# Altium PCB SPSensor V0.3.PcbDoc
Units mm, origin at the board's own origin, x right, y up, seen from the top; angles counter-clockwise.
Board outline 22.01 x 110.07 mm, 4 copper layers (TopLayer, GND, PWR, BottomLayer); 88 components, 66 nets, 299 pads, 113 vias.
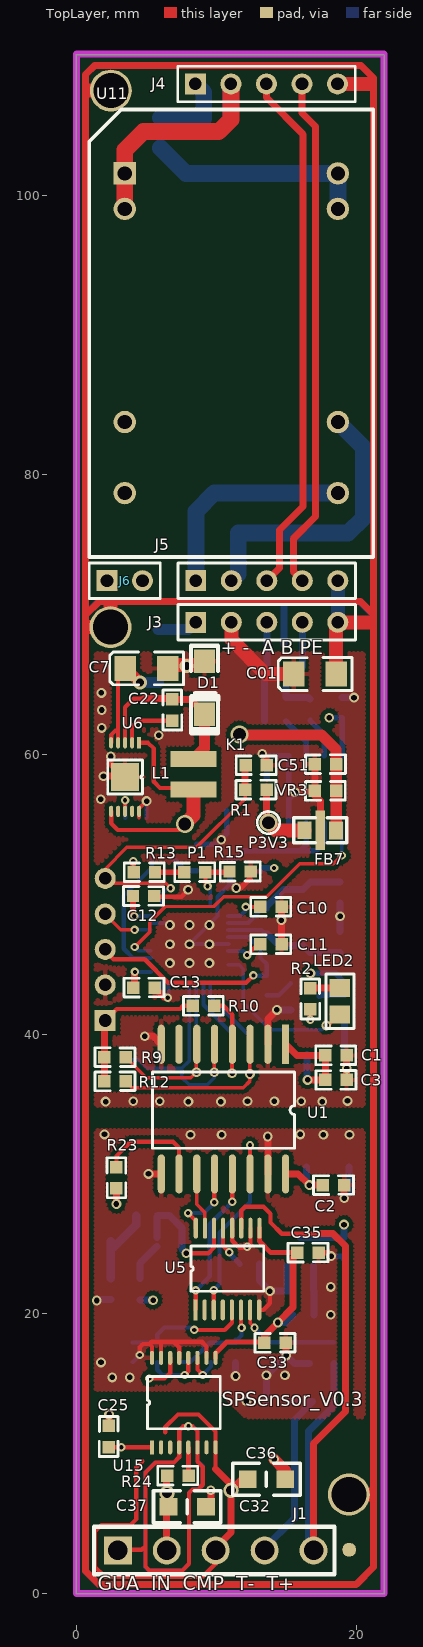
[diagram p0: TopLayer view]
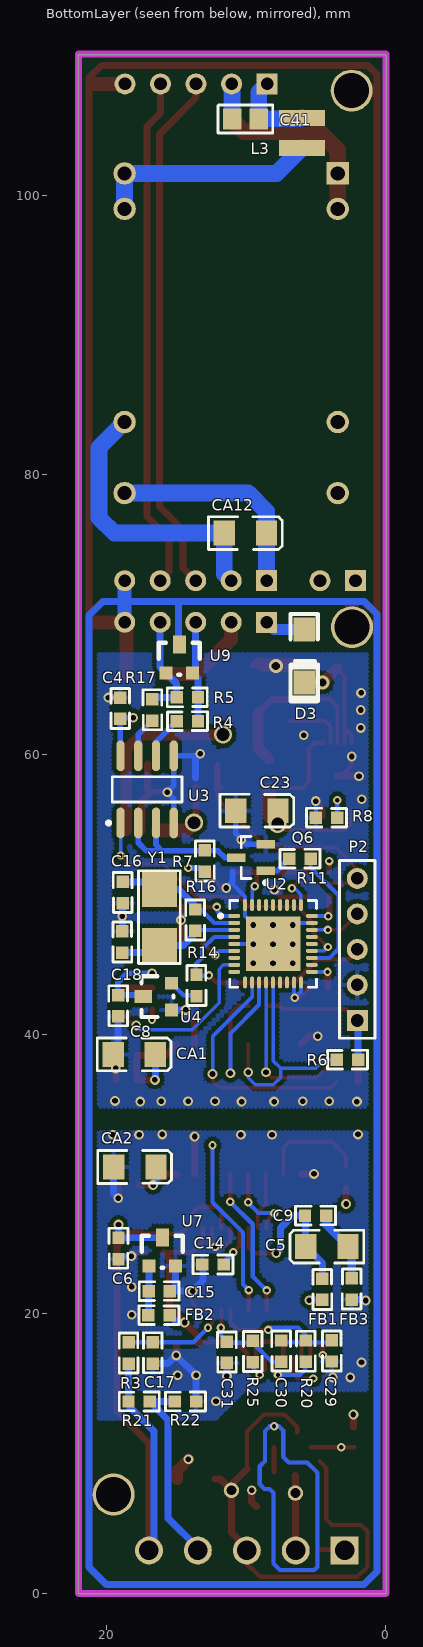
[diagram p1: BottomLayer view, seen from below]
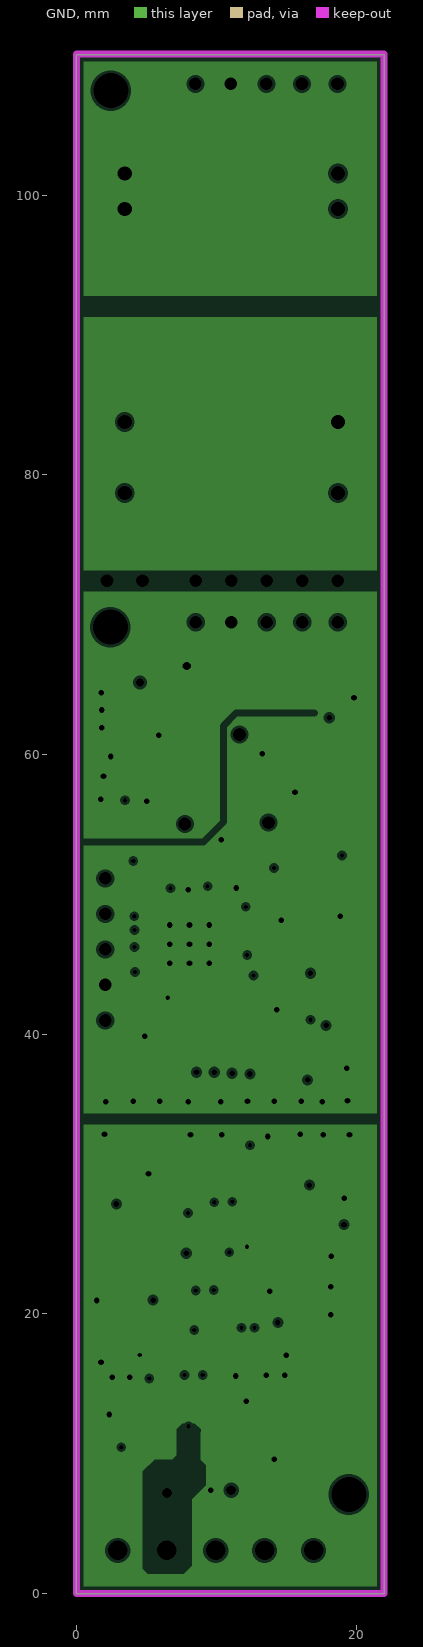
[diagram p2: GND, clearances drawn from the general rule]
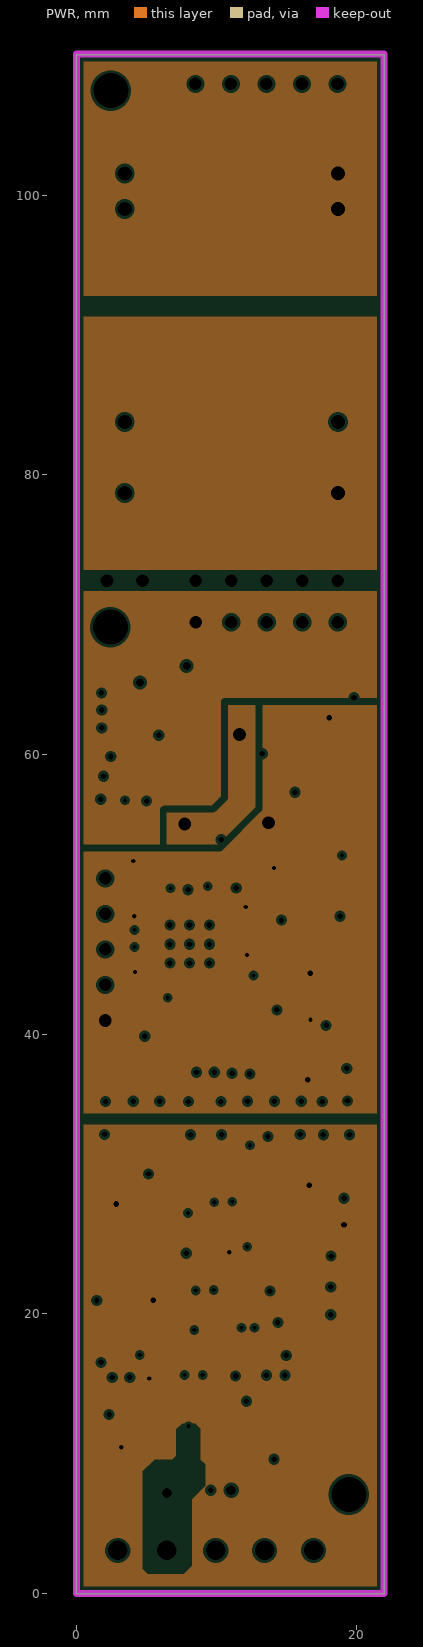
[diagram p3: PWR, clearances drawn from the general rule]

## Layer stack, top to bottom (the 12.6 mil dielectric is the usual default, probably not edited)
TopLayer: signal copper 0.0356
Dielectric: core 0.32, FR-4, Dk 4.8
GND: plane copper 0.0356, net (Multiple Nets)
Dielectric: prepreg 0.32, FR-4, Dk 4.8
PWR: plane copper 0.0356, net (Multiple Nets)
Dielectric: core 0.32, FR-4, Dk 4.8
BottomLayer: signal copper 0.0356

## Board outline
-0.006,-0.025 22,-0.025 22,110.05 -0.006,110.05

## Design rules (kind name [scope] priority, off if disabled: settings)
Clearance Clearance_poly [InPolygon] p1: gap=0.3
Clearance [All] p2: gap=0.15
ComponentClearance [All] p1: gap=0.15 collisioncheckmode=3 verticalgap=0.254 showdistances=FALSE
FabricationTestPointUsage TestPointUsage [All] p1: valid=0 allowmultiple=FALSE
FabricationTestpoint Testpoint [All] p1: side=3 testpointundercomponent=TRUE minsize=1.016 maxsize=2.54 preferedsize=1.524 minholesize=0.508 maxholesize=1.016 preferedholesize=0.813 testpointgrid=0.025 allowsidetop=TRUE allowsidebottom=TRUE usegrid=TRUE gridtolerance=0
HoleSize [All] p1: absolutevalues=TRUE maxlimit=5.08 minlimit=0.025 maxpercent=80.000 minpercent=20.000
MinimumSolderMaskSliver [All] p1: minsoldermaskwidth=0.15
PlaneClearance [All] p1: clearance=0.2
PlaneConnect [All] p1: planeconnectstyle=Relief reliefexpansion=0.3 reliefentries=4 reliefconductorwidth=0.3 reliefairgap=0.3
PolygonConnect PolygonConnect_via [IsVia] p1: connectstyle=Direct reliefconductorwidth=0.254 reliefentries=4 polygonreliefangle="90 Angle"
PolygonConnect [All] p2: connectstyle=Relief reliefconductorwidth=0.3 reliefentries=4 polygonreliefangle="90 Angle"
RoutingVias [All] p1: holewidth=0.305 width=0.61 viastyle="Through Hole" minholewidth=0.254 minwidth=0.508 maxholewidth=2 maxwidth=5
SilkToSilkClearance [All] p1: silktosilkclearance=0
SilkscreenOverComponentPads [All] p1: minsilkscreentomaskgap=0
SolderMaskExpansion [All] p1: expansion=0.102
Width [All] p1: maxlimit=5.08 minlimit=0.1 preferedwidth=0.254
19 further rules are at their usual default settings.

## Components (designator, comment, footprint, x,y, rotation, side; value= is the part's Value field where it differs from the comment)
C1 "10nF" SM0603 18.55,38.525 r0 top
C01 "1nF/2kV" SM1206 17.05,65.75 r180 top
C2 "0.1uF" SM0603 18.375,29.25 r0 top
C3 "0.1uF" SM0603 18.55,36.675 r180 top
C4 "0.1uF" SM0603 19.05,63.3 r90 bottom
C5 "10uF" SM1206 4.225,24.8 r0 bottom
C6 "4.7uF" SM0603 19.075,24.675 r270 bottom
C7 "4.7uF/50V" SM1206 5,66.15 r180 top
C8 "0.1uF" SM0603 19.1,42.025 r270 bottom
C9 "0.1uF" SM0603 5.025,27.075 r180 bottom
C10 "0.1uF" SM0603 13.9,49.15 r0 top
C11 "0.1uF" SM0603 13.9,46.475 r0 top
C12 "0.1uF" SM0603 4.8,49.925 r0 top
C13 "0.1uF" SM0603 4.825,43.375 r0 top
C14 "0.1uF" SM0603 12.375,23.475 r0 bottom
C15 "1uF" SM0603 16.21,21.675 r180 bottom
C16 "22pF" SM0603 18.775,50.125 r270 bottom
C17 "1uF" SM0603 16.625,17.2 r270 bottom
C18 "22pF" SM0603 18.9,46.59 r90 bottom
C22 "0.47uF" SM0603 6.8,63.175 r90 top
C23 "22uF" SM1206 9.225,55.975 r180 bottom
C25 "0.1uF" SM0603 2.25,11.225 r90 top
C29 "1uF" SM0603 3.925,17.35 r90 bottom
C30 "100pF" SM0603 7.45,17.325 r270 bottom
C31 "1uF" SM0603 11.325,17.25 r270 bottom
C33 "0.1uF" SM0603 14.2,17.975 r0 top
C35 "0.1uF" SM0603 16.55,24.425 r0 top
C36 "1nF" 0805A 12.241,8.172 r0 top
C37 "1nF" 0805A 6.575,6.2 r0 top
C41 "1uF/50V" SM0805 10.025,105.475 r0 bottom
C51 "0.1uF" SM0603 17.8,59.25 r180 top
CA1 "10uF" SM1206 18,38.55 r180 bottom
CA2 "10uF" SM1206 17.96,30.5 r180 bottom
CA12 "10uF/50V" SM1206 10.05,75.825 r180 bottom
D1 "CD1607-B140" 1206D 9.15,66.475 r270 top
D3 "M7" 1206D 5.85,68.75 r270 bottom
FB1 "BLM18PG600SN1" SM0603 4.6,21.75 r90 bottom
FB2 "BLM18PG600SN1" SM0603 16.225,19.95 r180 bottom
FB3 "BLM18PG600SN1" SM0603 2.5,21.775 r90 bottom
FB7 "NFM21PC105B1C3" NFM21PC105 18.575,54.575 r180 top
J1 "Header 5" CON1x5-3.5mm 2.95,3.075 r0 top
J3 "Header 5" HDR1X5 8.525,69.45 r0 top
J4 "Header 5" HDR1X5 8.5,107.95 r0 top
J5 "Header 5" HDR1X5 8.525,72.425 r0 top
J6 "Header 5" HDR1X2 2.175,72.425 r0 top (schematic designator J5)
K1 "KEY1" SM0603 12.85,59.175 r180 top (schematic designator R1)
L1 "LPS3010-472ML" LPS3010 8.375,59.666 r270 top
L3 "4.7uH" LPS3010 6,105.525 r270 bottom
LED2 "RUN" SM0805 18.8,42.375 r270 top
P1 "NC" sm0603 8.45,51.525 r180 top
P2 "Header 5" HDR1X5 2.05,40.975 r90 bottom
P3V3 "TestPoint" "test point" 13.725,55.125 r90 top
Q6 "MMBT3904" SOT23_N 9.65,52.625 r0 bottom
R1 "10K" SM0603 12.825,57.425 r180 top
R2 "560R" SM0603 16.675,42.525 r90 top
R3 "10K" SM0603 18.45,17.2 r90 bottom
R4 "10R" SM0603 14.2,62.325 r0 bottom
R5 "120R" SM0603 14.2,64.125 r180 bottom
R6 "100K" SM0603 2.75,38.125 r0 bottom
R7 "4.7K" SM0603 12.9,52.375 r270 bottom
R8 "49.9K" SM0603 4.25,55.525 r180 bottom
R9 "100K" SM0603 2.75,38.4 r0 top
R10 "100K" SM0603 9.075,42.075 r0 top
R11 "1K" SM0603 6.15,52.5 r0 bottom
R12 "100K" SM0603 2.75,36.675 r0 top
R13 "1K" SM0603 4.85,51.625 r0 top
R14 "1K" SM0603 13.6,43.475 r90 bottom
R15 "100K" SM0603 11.7,51.575 r180 top
R16 "10M" SM0603 13.6,48.15 r270 bottom
R17 "10R" SM0603 16.65,63.185 r270 bottom
R20 "10K" SM0603 5.775,17.325 r90 bottom
R21 "NC" SM0603 17.65,13.675 r0 bottom
R22 "0R" SM0603 14.34,13.675 r0 bottom
R23 "4.7K" SM0603 2.9,29.725 r270 top
R24 "10M" SM0603 7.25,8.475 r0 top
R25 "10K" SM0603 9.575,17.3 r90 bottom
U1 "ADuM5401ARWZ" ADUM1401 14.95,39.275 r270 top
U2 "STM32F103T8U6" VFQN36_V 8.075,46.45 r180 bottom
U3 "MAX3485CSA" NSO8_N 17.075,57.5 r90 bottom
U4 "CAT809VTBI-GT3" SOT-23 17.475,44.061 r90 bottom
U5 "AD7793BRU" AD7793 10.795,23.2 r90 top
U6 "LT3971IMSE-3.3" LT3971 3.475,58.381 r180 top
U7 "AD1584BRTZ" SOT-23 14.614,25.575 r180 bottom
U9 "SM712.TCT" SOT-23 13.4,67.975 r180 bottom
U11 "URB2424ZP-6WR3" URB2424ZP-6WR3 3.45,101.55 r270 top locked
U15 "LMP91200" LMP91200 7.67,13.65 r0 top
VR3 "V3.5MLA0603N" SM0603 17.8,57.45 r0 top (schematic designator VA2)
Y1 "8MHz" CY5.4X4.6 16.2,50.325 r270 bottom

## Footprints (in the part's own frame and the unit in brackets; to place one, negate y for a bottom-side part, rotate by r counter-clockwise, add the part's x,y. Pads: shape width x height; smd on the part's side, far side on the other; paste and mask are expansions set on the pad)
0805A [mm]
  rect 1.27x1.27 smd: 1(0,0) 2(2.678,0)
  silkscreen extent -1.07,-1.14 3.75,1.14
1206D [mm]
  rect 1.7x1.524 smd: 1(-0.19,0.003) 2(3.61,0.003)
  silkscreen extent -1.3,-0.97 4.96,0.99
AD7793 [mm]
  rect 1.5x0.3 smd: 1(-2.921,2.286)
  oval 1.5x0.3 smd: 2(-2.921,1.636) 3(-2.921,0.986) 4(-2.921,0.336) 5(-2.921,-0.314) 6(-2.921,-0.964) 7(-2.921,-1.614) 8(-2.921,-2.264) 9(2.921,-2.286) 10(2.921,-1.636) 11(2.921,-0.986) 12(2.921,-0.336) 13(2.921,0.314) 14(2.921,0.964) 15(2.921,1.614) 16(2.921,2.264)
  silkscreen extent -1.59,-2.59 1.64,2.61
ADUM1401 [mm]
  rect 2.8x0.51 smd: 1(0,0)
  oval 2.8x0.51 smd: 2(0,-1.27) 3(0,-2.54) 4(0,-3.81) 5(0,-5.08) 6(0,-6.35) 7(0,-7.62) 8(0,-8.89) 9(9.271,-8.89) 10(9.271,-7.62) 11(9.271,-6.35) 12(9.271,-5.08) 13(9.271,-3.81) 14(9.271,-2.54) 15(9.271,-1.27) 16(9.271,0)
  silkscreen extent 1.99,-9.53 7.43,0.64
CON1x5-3.5mm [mm]
  rect 2x2 hole 1.4: 1(0,0)
  round 2 hole 1.4: 2(3.5,0) 3(7,0) 4(10.5,0) 5(14,0)
  silkscreen extent -1.7,-1.7 15.5,1.7
CY5.4X4.6 [mm]
  rect 2.5x2.5 smd: 1(-0.025,0) 2(4,0)
  silkscreen extent -1.35,-1.49 5.28,1.49
HDR1X2 [mm] "Connector; Header; 2 Position"
  rect 1.5x1.5 hole 0.9: 1(0,0)
  round 1.5 hole 0.9: 2(2.54,0)
  silkscreen extent -1.27,-1.27 3.81,1.27
HDR1X5 [mm] "Connector; Header; 5 Position"
  rect 1.5x1.5 hole 0.9: 1(0,0)
  round 1.5 hole 0.9: 2(2.54,0) 3(5.08,0) 4(7.62,0) 5(10.16,0)
  silkscreen extent -1.27,-1.27 11.43,1.27
LMP91200 [mm]
  rect 0.3x1 smd: 1(-2.275,-3.2)
  oval 0.3x1 smd: 2(-1.625,-3.2) 3(-0.975,-3.2) 4(-0.325,-3.2) 5(0.325,-3.2) 6(0.975,-3.2) 7(1.625,-3.2) 8(2.275,-3.2) 9(2.275,3.2) 10(1.625,3.2) 11(0.975,3.2) 12(0.325,3.2) 13(-0.325,3.2) 14(-0.975,3.2) 15(-1.625,3.2) 16(-2.275,3.2)
  silkscreen extent -2.6,-1.87 2.6,1.87
LPS3010 [mm]
  rect 1.14x3.3 smd: 1(0,0) 2(2.16,0)
LT3971 [mm]
  rect 0.28x0.8 smd: 1(-1,-2.45)
  oval 0.28x0.8 smd: 2(-0.5,-2.45) 3(0,-2.45) 4(0.5,-2.45) 5(1,-2.45) 6(1,2.45) 7(0.5,2.45) 8(0,2.45) 9(-0.5,2.45) 10(-1,2.45)
  rect 2x2 smd: 11(0,0)
  silkscreen extent -1.25,-1.21 1.25,1.22
NFM21PC105 [mm]
  rect 1x1.27 smd: 1(0.01,0.008) 2(2.286,0)
  rect 0.7x2.8 smd: 3(1.143,0)
  silkscreen extent -0.76,-0.89 3.05,0.89
NSO8_N [mm] "SOIC, 8-Leads, Body 4.9x3.9mm, Pitch 1.27mm, IPC Medium Density"
  oval 2.2x0.6 smd: 1(-2.4,1.905) 2(-2.4,0.635) 3(-2.4,-0.635) 4(-2.4,-1.905) 5(2.4,-1.905) 6(2.4,-0.635) 7(2.4,0.635) 8(2.4,1.905)
  silkscreen extent -2.52,-2.5 0.9,2.88, body extent -2,-2.5 2,2.5, height 1.75
SM0603 [mil]
  rect 35x35 smd: 1(-30,-2) 2(30,-2)
  silkscreen extent -57,-28 56,24
sm0603 [mil]
  rect 35x35 smd: 1(-30,-2) 2(30,-2)
  silkscreen extent -57,-28 56,24
SM0805 [mm]
  rect 1.3x1.5 smd: 1(-0.933,0.022) 2(0.967,0.022)
  silkscreen extent -1.93,-0.97 1.98,1.04
SM1206 [mil]
  rect 60x70 smd: 1(59.5,0) 2(-59.5,0)
  silkscreen extent -104,-46 104,46
SOT23_N [mm] "SOT23, 3-Leads, Body 2.9x1.3mm, Pitch 0.95mm, Lead Span 2.3mm, IPC Medium Density"
  rect 1.3x0.6 smd: 1(-1.05,0.95) 2(-1.05,-0.95) 3(1.05,0)
  silkscreen extent -1.17,-1.5 0.7,1.92, body extent -0.7,-1.5 0.7,1.5, height 1.1
SOT-23 [mil]
  rect 36x36 smd: 1(-91.86,-84.66) 2(-16.86,-84.66)
  rect 36x50 smd: 3(-53.86,-4.66)
  silkscreen extent -112,-90 3,0
"test point" [mm]
  round 1.3 hole 0.9: 1(0,0)
  silkscreen extent -0.8,-0.8 0.8,0.8
URB2424ZP-6WR3 [mm] "isolated DC-DC converter, 6W"
  rect 1.6x1.6 hole 1.016: 2(0,0)
  round 1.6 hole 1.016: 3(2.54,0) 9(17.78,0) 11(22.86,0) 14(22.86,15.24) 16(17.78,15.24) 22(2.54,15.24) 23(0,15.24)
  silkscreen extent -4.57,-2.54 27.43,17.78
VFQN36_V [mm] "QFN, 36-Leads, Body 6x6mm, Pitch 0.5mm, ST Recommended"
  oval 0.85x0.3 smd: 1(-2.775,2) 2(-2.775,1.5) 3(-2.775,1) 4(-2.775,0.5) 5(-2.775,0) 6(-2.775,-0.5) 7(-2.775,-1) 8(-2.775,-1.5) 9(-2.775,-2) 19(2.775,-2) 20(2.775,-1.5) 21(2.775,-1) 22(2.775,-0.5) 23(2.775,0) 24(2.775,0.5) 25(2.775,1) 26(2.775,1.5) 27(2.775,2)
  oval 0.3x0.85 smd: 10(-2,-2.755) 11(-1.5,-2.755) 12(-1,-2.755) 13(-0.5,-2.755) 14(0,-2.755) 15(0.5,-2.755) 16(1,-2.755) 17(1.5,-2.755) 18(2,-2.755) 28(2,2.775) 29(1.5,2.775) 30(1,2.775) 31(0.5,2.775) 32(0,2.775) 33(-0.5,2.775) 34(-1,2.775) 35(-1.5,2.775) 36(-2,2.775)
  rect 3.9x3.9 smd: 37(0,0)
  silkscreen extent -3.88,-3.1 3.1,3.1, body extent -3.05,-3.05 3.05,3.05, height 1

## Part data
C1 C01 C6 C7 C9 C14 C15 C22 C25 C29 C30 C31 C33 C35 C36 C37 C41 C51: library part CAP, "Capacitor"
C2 C3: library part CA, "电?"
C4 C8: library part Cap, "Capacitor, X7R Ceramic"
C5: library part CAPE, "极?"
C10 C11 C12 C13 C16 C18: library part Cap, "Capacitor"
C17: library part CAP, "电?"
C23: library part C, "极?"
CA1 CA2 CA12: library part CAPE, "Capacitor"
D1: library part DIODE, "Diode"
D3: library part "Diode 1N4007", "1 Amp General Purpose Rectifier"
FB1 FB3 L1 L3: library part INDUCTOR
FB2 FB7: library part Inductor, "Inductor"
J1 J3 J4 J5 J6 P2: "Header, 5-Pin"
K1: library part "Header 2", "Header, 2-Pin"
LED2: library part LED0, "Typical INFRARED GaAs LED"
P1: library part Hea, "Header, 2-Pin, 2.54mm, 排?"
Q6: "NPN Switching Transistor"
R1 R2 R4 R5 R7 R11 R16 R17: library part Res2, "Resistor"
R3 R6 R9 R10 R12 R20 R21 R22 R25: library part RES, "电?"
R8 R13 R14 R15 R23: library part RE, "电?"
R24: library part R, "电?"
U1: library part ADUM1401, "1Mbps Data Rate, 100ns Propagation delay"
U2: "STM32 ARM-based 32-bit MCU with 64 Kbytes Flash, 36-pin VFQFPN, Industrial Temperature"
U3: library part MAX485CSA, "Low-Power, Slew-Rate-Limited RS-485/RS-422 Transceiver"
U4: library part CAT8, "On"
U5: library part AD7793
U6: library part LT3971
U7: library part "Header 3", "4.096V reference"
U9: library part "Header 3", "Asymmerical TVS Diode for RS485"
VR3: library part "D Zener", "Zener Diode"
Y1: library part XTAL, "Crystal Oscillator"

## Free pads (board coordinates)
  round 1 smd: 0(19.5,3.125)
  round 3 hole 2.5: ""(2.425,69.1) ""(2.45,107.475) ""(19.475,7.075)
  round 1.1 hole 0.7: ""(6.475,7.175) ""(11.05,7.375)

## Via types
v1: diameter 0.7, hole 0.4, TopLayer to BottomLayer, 77 vias
v2: diameter 0.6, hole 0.3, TopLayer to BottomLayer, 32 vias
v3: diameter 1.3, hole 0.9, TopLayer to BottomLayer, 2 vias
v4: diameter 1, hole 0.6, TopLayer to BottomLayer, 2 vias

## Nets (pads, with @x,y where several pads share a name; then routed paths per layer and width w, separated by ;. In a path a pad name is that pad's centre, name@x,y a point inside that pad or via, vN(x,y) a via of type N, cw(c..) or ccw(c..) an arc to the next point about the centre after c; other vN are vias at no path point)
24VGND_IN: C41.2 J4.2 U11.2 U11.3 | length 17.8
  TopLayer w1.2: U11.3 U11.2 3.45,103.225 4.775,104.55 10.175,104.55 11.04,105.415 J4.2
  BottomLayer w1.2: C41.2 10.992,107.902 J4.2
+24V: D3.1 J3.1 | length 2.9
  BottomLayer w0.8: D3.1 8.015,68.941 J3.1
+24V_1: CA12.1 J5.1 U11.14 | length 15.7
  BottomLayer w1.2: J5.1@8.55,72.425 8.539,72.436 CA12.1 8.539,77.389 9.84,78.69 U11.14
+24V_IN: C41.1 J4.1 L3.1 | length 5.9
  BottomLayer w1.2: L3.1 6.072,105.453 C41.1 9.092,107.358 J4.1
BOOT0: P1.1 R15.2 U2.35 | length 4.3
  TopLayer w0.3: P1.1 9.212,50.738 v2(9.375,50.575)
  TopLayer w0.4: P1.1@9.262,51.576 R15.2@10.977,51.576
  BottomLayer w0.25: v2(9.375,50.575) 9.575,50.375 U2.35
  BottomLayer w0.3: v2(9.375,50.575) v2@9.375,50.675
DVDD: C5.1 C9.1 FB1.2 U5.14 | length 12
  TopLayer w0.3: v1(7.85,24.325) 9.425,24.325 9.831,24.731 U5.14
  BottomLayer w0.5: FB1.2 4.549,23.613 C5.1 ; C5.1@5.736,25.45 5.736,26.973 C9.1 6.651,27.024 7.525,26.15 7.525,24.65 v1(7.85,24.325)
EARTH: C01.2 J3.5 J4.5 J5.5 pad.@2.45,107.475 pad.@2.425,69.1 pad.@19.475,7.075 U9.3 | length 477.8
  TopLayer w0.3: J3.5@18.685,69.55 J3.5@18.81,69.675
  TopLayer w0.5: 0.644,70.056 0.644,108.619 1.3,109.275 20.344,109.275 21.25,108.369 21.25,70 ; 21.25,70 20.3,70.95 1.625,70.95 0.644,69.969 0.644,1.606 1.6,0.65 20,0.65 21.25,1.9 21.25,70
  TopLayer w1: 0.894,69.1 2.425,69.1 pad.@2.425,70.575 ; 0.919,107.475 pad.@2.45,107.475 ; C01.2 18.561,69.326 J3.5 20.975,69.45 ; J4.5 21,107.95 ; pad.@19.475,7.075 pad.@20.925,7.075
  BottomLayer w0.5: U9.3@14.843,67.857 14.843,70.618 ; 0.65,1.575 1.575,0.65 20,0.65 21.25,1.9 21.25,69.925 20.225,70.95 18.685,70.95 1.55,70.95 0.65,70.05 0.65,1.575
  BottomLayer w1: J3.5 18.685,70.95 J5.5 ; pad.@19.475,7.075 pad.@20,7.075
GND: C01.1 C1.2 C3.1 C4.2 C7.2 C8.2 C10.2 C11.2 C12.2 C13.2 C16.2 C18.2 C23.2 C51.2 CA1.2 D1.1 FB7.3 J3.2 K1.1 P2.2 Q6.2 R8.1 R15.1 U1.2 U1.8 U2.5 U2.17 U2.18 U2.26 U2.36 U2.37 U3.4 U3.5 U4.1 U6.10 U6.11 VR3.1 | length 70.8
  TopLayer w0.3: v1@2.475,59.85 2.475,59.191 U6.11@3.225,58.441 ; 4.475,55.506 U6.10 4.475,56.125 v1(5.012,56.662) ; C12.2 5.611,49.825 7.5,49.825 7.975,50.3 v1(7.975,50.325)
  TopLayer w0.4: D1.1@9.153,66.74 D1.1@9.544,66.349 ; v1(11.425,50.45) 11.725,50.45 12.375,51.1 R15.1@12.375,51.575 ; v1@13.25,60.025 13.587,59.688 K1.1@13.587,59.199 ; v1@15.625,57.325 VR3.1@16.762,57.325
  TopLayer w0.5: v1@1.887,58.441 v1(1.925,58.441) 3.225,58.441 U6.11@3.469,58.441 ; v1(4.875,39.85) 5.485,39.85 U1.8 ; C13.2 6.311,42.6 v2(6.525,42.6) ; U1.2 13.68,41.08 v1(14.328,41.728) ; C11.2 C10.2 ; VR3.1@16.762,57.325 17.432,56.655 FB7.3 ; VR3.1 C51.2 ; C3.1 C1.2
  TopLayer w1: C7.2@6.615,66.4 v4@7.875,66.4 ; v4(7.875,66.325) v4@7.875,66.4 ; D1.1@8.812,66.4 v4@7.875,66.4 ; J3.2 11.065,68.21 13.525,65.75 C01.1
  BottomLayer w0.3: R8.1 v1(5.012,56.662) ; U2.26 U2.37@6.575,47.95 ; U2.18 6.075,43.05 v2(6.525,42.6) 6.575,42.65 U2.17 ; U2.5 U2.37 10.075,48.45 U2.36 10.075,49.825 10.975,50.725 10.975,50.9
  BottomLayer w0.4: Q6.2 9.975,53.575 10.736,54.336 C23.2 ; 10.975,51.625 10.975,50.9 v1(11.425,50.45) ; v1@13.425,59.9 U3.5 15.17,57.78 15.663,57.288 15.65,57.275 15.17,56.795 U3.4
  BottomLayer w0.5: v1(13.275,60.05) 13.425,59.9 13.602,59.723 13.602,58.326 ; v1(14.328,41.728) U4.1 ; C16.2 18.849,49.34 v1(18.849,48.425) C18.2 ; C4.2 v1(19.838,64.062) ; C8.2 19.151,38.91 CA1.2 19.325,38.364 v1(19.325,37.55)
  other v1: 2.075,35.175 8,35.175 10.325,35.175 17.575,35.175 4.05,35.2 5.95,35.2 12.225,35.2 14.15,35.2 16.075,35.2 19.375,35.225 6.675,45.075 8.075,45.075 9.5,45.075 6.675,46.425 8.075,46.425 9.5,46.425 6.675,47.8 8.075,47.8 9.5,47.8 14.65,48.15 10.35,53.9 1.725,56.8 15.625,57.3 2.45,59.85 5.875,61.375 1.8,61.9 1.8,63.175 1.775,64.4
GND_1: CA12.2 J5.2 U11.16 | length 20.6
  BottomLayer w1.2: J5.2@11.09,72.425 11.561,72.896 CA12.2 19.425,75.825 20.525,76.925 20.525,81.935 U11.16
GND_ISO: C2.2 C6.2 C14.2 C15.2 C17.2 C25.2 C29.1 C31.2 C33.2 C35.2 C36.2 C37.2 CA2.2 FB3.1 R22.1 U1.9 U1.15 U5.8 U5.10 U5.12 U7.2 U15.10 U15.13 U15.15 U15.16 | length 43.6
  TopLayer w0.3: v2(4.525,17.051) 4.525,17.625 4.733,17.833 5.208,17.833 ; U15.16 5.395,17.647 5.208,17.833 ; U15.15 6.045,17.925 5.969,18 ; U15.13 7.345,17.6 6.944,18 ; U15.10 9.295,17.655 8.95,18 6.944,18 ; U5.12 11.131,25.219 11.65,24.7 12.1,24.7 12.431,25.031 U5.10 ; U5.8 13.354,20.279 13.825,20.75 v1(13.825,21.625) ; 5.208,17.833 5.375,18 5.969,18 ; 5.969,18 6.944,18
  TopLayer w0.4: C35.2@17.272,24.375 17.95,24.375 v1(18.2,24.125)
  TopLayer w0.5: C25.2@2.325,11.897 v1(2.325,12.8) ; v1(5.146,30.004) U1.9 ; C37.2 9.6,6.547 v1(9.6,7.375) ; U1.15 v1(13.68,32.68) ; v1@14.925,17.025 v1@14.962,17.025 ; C33.2 v1@14.962,17.025 ; v1(15,17.025) v1@14.962,17.025 ; v1(19.137,28.263) C2.2
  TopLayer w0.8: v1(14.125,9.6) 14.92,8.805 C36.2
  BottomLayer w0.3: C29.1@4,16.553 4.027,16.553 v2(4.525,17.051)
  BottomLayer w0.4: v1(18.2,24.125) 18.914,24.125 C6.2
  BottomLayer w0.5: v1(1.45,20.951) 1.512,21.013 FB3.1 ; v1@11.375,15.725 C31.2@11.375,16.525 ; C14.2@13.072,23.55 13.072,22.378 v1(13.825,21.625) C15.2 ; R22.1 v1(13.578,15.603) v1(15,17.025) 15.587,16.438 C17.2 ; U7.2 15.042,22.03 C15.2 ; C15.2 C15.2 ; v1(19.137,28.263) 19.472,28.598 CA2.2
  other v1: 12.15,13.75 2.55,15.45 3.8,15.45 11.375,15.55 14.9,15.6 1.75,16.525 18.175,19.925 18.175,21.925 8.15,32.8 10.375,32.8 17.65,32.8 19.519,32.8 2,32.825 16,32.825
  other v2: 12.2,24.8
GUARD: J1.1 U15.4 U15.6 | length 55.5
  TopLayer w0.3: J1.1@3.05,3.125 4.65,3.125 4.925,3.4 ; U15.6 8.645,11.605 8.3,11.95 v2(8,11.95) 7.625,11.95 7.345,11.67 U15.4 7.345,9.745 6.975,9.375 5.65,9.375 4.925,8.65 4.925,3.4 ; U15.6@8.65,10.45 8.65,9.425 9.025,9.05 9.025,7.775 8.675,7.425 8.3,7.425 8.05,7.175 8.05,2.125 7.575,1.65 5.2,1.65 4.925,1.925 4.925,3.4
  BottomLayer w0.3: 4.9,1.9 5.125,1.675 7.575,1.675 8.05,2.15 8.05,7.2 8.325,7.475 8.675,7.475 9.025,7.825 9.025,9.1 8.65,9.475 8.65,11.625 8.325,11.95 v2(8,11.95) 7.65,11.95 7.35,11.65 7.35,9.775 6.95,9.375 5.625,9.375 4.9,8.65 4.9,1.9
JTCK: K1.2 P2.5 R1.2 U2.28 | length 22
  TopLayer w0.25: v2(6.725,50.425) 6.375,50.775 2.41,50.775 P2.5 2.05,51.8 3.6,53.35 8.575,53.35 12.063,56.838 R1.2
  TopLayer w0.3: R1.2@11.776,57.676 R1.2@12.063,57.676
  TopLayer w0.5: R1.2 12.063,57.676 K1.2@12.063,59.199
  BottomLayer w0.25: U2.28 6.075,49.975 6.525,50.425 v2(6.725,50.425)
JTDI: U2.29
JTDO: U2.30
JTMS: P2.4 U2.25 | length 3.8
  TopLayer w0.25: P2.4@2,48.6 3.15,47.45 v2(4.15,47.45)
  BottomLayer w0.25: v2(4.15,47.45) U2.25
JTRST: U2.31
LED_S1: U2.23
LED_S2: LED2.2 U2.8 | length 12.4
  TopLayer w0.25: v1(17.85,40.625) 18.039,40.625 LED2.2 LED2.2@18.208,41.408
  BottomLayer w0.25: U2.8 11.625,44.95 11.925,44.65 11.925,42.25 13.85,40.325 17.55,40.325 v1(17.85,40.625)
MCU_RXD1: U2.22 U3.1 | length 21.5
  TopLayer w0.25: v2(4.15,46.225) 5.225,47.3 5.225,48 6.35,49.125 9.825,49.125 10.525,49.825 13.6,49.825 15.95,52.175 18.375,52.175 v2(18.975,52.775)
  BottomLayer w0.25: v2(4.15,46.225) 4.425,45.95 U2.22 ; v2(18.975,52.775) 18.98,52.78 U3.1
MCU_TXD1: R11.1 U2.21 | length 9.5
  BottomLayer w0.3: U2.21 4.025,45.45 3.375,46.1 3.375,49.9 5.388,51.913 R11.1
MISO1: R9.2 U1.6 U2.13 | length 14.5
  TopLayer w0.25: R9.2 4.986,36.875 8.175,36.875 v1(8.575,37.275) ; v1@8.575,37.15 v1(8.575,37.275) ; U1.6 8.575,39.25 v1(8.575,37.275)
  BottomLayer w0.25: v1@8.575,37.15 v1(8.575,37.275) U2.13
MOSI1: R6.2 U1.5 U2.14 | length 16.5
  TopLayer w0.25: v1(9.85,37.275) 9.85,39.255 U1.5 U1.5@9.862,39.283
  BottomLayer w0.25: R6.2 4.399,38.176 5.025,37.55 7.525,37.55 ; U2.14 8.075,38.1 7.525,37.55 ; v1(9.85,37.275) 9.85,36.875 9.35,36.375 8.05,36.375 7.525,36.9 7.525,37.55
NetC5_2: C5.2 C9.2 FB3.2 | length 5.5
  BottomLayer w0.6: FB3.2 2.449,24.699 C5.2@2.45,25.186 ; C5.2 4.263,26.349 C9.2
NetC7_1: C7.1 D3.2 U6.4 U6.5 | length 9.5
  TopLayer w0.3: U6.5 2.475,61.4 2.775,61.7 2.969,61.7 ; U6.4@2.969,60.799 2.969,61.7 ; C7.1 3.489,66.114 2.969,65.594 2.969,61.7
  TopLayer w0.8: C7.1 3.525,66.15 v4(4.535,65.141)
  BottomLayer w0.8: v4(4.535,65.141) D3.2
NetC15_1: C15.1 FB2.1 U7.1 | length 3.5
  BottomLayer w0.5: U7.1 16.947,21.649 C15.1 FB2.1@16.972,19.914
NetC16_1: C16.1 R16.1 U2.2 Y1.1 | length 9.1
  BottomLayer w0.3: U2.2 12.275,47.95 13.237,48.912 R16.1
  BottomLayer w0.5: R16.1@13.651,49.201 14.8,50.35 Y1.1 16.737,50.887 C16.1
NetC17_1: C17.1 R3.2 U5.7 | length 7.5
  TopLayer w0.25: U5.7 12.409,19.316 v2(12.725,19)
  BottomLayer w0.3: v2(12.725,19) 13.763,17.962 C17.1 R3.2
NetC18_1: C18.1 R16.2 U2.3 Y1.2 | length 8.7
  BottomLayer w0.3: U2.3 13.235,47.45 13.423,47.262 R16.2@13.651,47.262
  BottomLayer w0.5: R16.2@13.651,47.162 14.488,46.325 Y1.2 ; Y1.2@16.163,46.288 Y1.2 ; C18.1 16.697,45.828 Y1.2
NetC22_1: C22.1 U6.2 | length 4.3
  TopLayer w0.3: U6.2@3.969,60.799 3.969,62 4.382,62.413 C22.1
NetC22_2: C22.2 D1.2 L1.1 U6.3 | length 12.6
  TopLayer w0.3: U6.3@3.469,60.799 3.469,63.375 4.077,63.983 4.825,63.983
  TopLayer w0.5: 4.825,63.983 C22.2@6.925,63.983 ; C22.2 8.156,63.937 D1.2@9.153,62.94
  TopLayer w0.8: L1.1 9.153,60.443 D1.2@9.153,62.94
NetC23_1: C23.1 C51.1 FB7.1 L1.2 U6.1 U6.6 VR3.2 | length 29
  TopLayer w0.3: U6.6 2.475,55.075 2.95,54.6 7.325,54.6 v3(7.75,55.025) ; U6.1 5.119,60.831 5.525,60.425 5.525,58.05 5.969,57.606 L1.2@8.375,57.606
  TopLayer w0.8: v3@11.65,61.4 17.525,61.4 18.562,60.363 C51.1 18.565,59.298 FB7.1
  TopLayer w1: v3(7.75,55.025) 8.375,55.65 L1.2
  other v3: 11.65,61.425
NetC29_2: C29.2 C30.1 R20.2 U5.5 | length 10.9
  TopLayer w0.3: v2(8.412,18.85) 10.6,18.85 11.109,19.359 U5.5
  BottomLayer w0.3: C29.2@4,17.95 R20.2@5.775,17.95 ; C30.1@7.55,17.95 R20.2@5.775,17.95 ; v2(8.412,18.85) 8.237,19.025 6.275,19.025 5.775,18.525 R20.2@5.775,17.95
NetC30_2: C30.2 C31.1 R25.2 U5.6 | length 7
  TopLayer w0.3: v2@11.759,19.034 U5.6
  BottomLayer w0.3: C30.2@7.55,16.553 8.153,16.553 9.525,17.925 11.372,17.925 11.375,17.922 C31.1@11.375,18.167 ; C31.1 11.8,18.436 v2(11.8,19)
NetL3_2: L3.2 U11.22 U11.23 | length 16
  BottomLayer w1.2: L3.2 7.815,101.55 U11.23 U11.22
NetLED2_1: LED2.1 R2.2 | length 2.1
  TopLayer w0.5: R2.2 18.801,43.287 LED2.1
NetP1_2: P1.2 R13.2 | length 2.3
  TopLayer w0.4: R13.2@5.447,51.625 5.496,51.576 P1.2@7.738,51.576
NetQ6_1: Q6.1 R11.2 | length 2.1
  BottomLayer w0.4: R11.2 7.788,51.675 Q6.1
NetQ6_3: Q6.3 R7.1 U3.2 U3.3 | length 11
  BottomLayer w0.4: Q6.3 11.525,52.625 12,53.1 16,53.1 ; U3.3 16.44,53.54 16,53.1 ; U3.2 17.71,53.685 17.125,53.1 16,53.1
NetR4_2: R4.2 U3.6 | length 3.1
  BottomLayer w0.4: R4.2 16.44,60.898 U3.6
NetR8_2: R8.2 U6.8 | length 2.1
  TopLayer w0.3: U6.8 v2(3.475,56.725)
  BottomLayer w0.3: v2(3.475,56.725) 3.488,56.712 R8.2
NetR14_1: R14.1 U4.2 | length 2.1
  BottomLayer w0.3: R14.1@13.6,42.775 14.466,42.775 U4.2
NetR17_2: R17.2 U3.7 | length 2.9
  BottomLayer w0.4: R17.2 17.71,61.414 U3.7
NetR20_1: R20.1 U15.12 | length 4
  TopLayer w0.3: v2(7.725,15.625) 7.995,15.895 U15.12
  BottomLayer w0.3: R20.1@5.775,16.553 5.775,16 6.15,15.625 v2(7.725,15.625)
NetR23_1: R23.1 U1.10 | length 7.7
  TopLayer w0.3: R23.1 2.849,31.274 3.875,32.3 6.9,32.3 7.33,31.87 U1.10
NetR24_2: R24.2 U15.5 | length 1.8
  TopLayer w0.35: R24.2@7.995,8.687 U15.5
NetR25_1: R25.1 U15.11 | length 2.5
  TopLayer w0.3: U15.11 8.645,16.005 v2(9.025,15.625)
  BottomLayer w0.3: v2(9.025,15.625) 9.625,16.225 R25.1@9.625,16.528
PH-CMP: C36.1 J1.3 pad.@11.05,7.375 U15.8 | length 36.2
  TopLayer w0.3: 4.725,9.45 4.275,9 4.275,5.325 3.85,4.9 1.775,4.9 1.325,4.45 1.325,1.9 2.025,1.2 9.025,1.2 9.95,2.125 J1.3@9.95,3.25 ; 6.344,11.525 6.344,11.895 7.25,12.8 8.725,12.8 9.945,11.58 U15.8 9.945,8.905
  TopLayer w0.5: 9.945,8.905 11.05,7.8 pad.@11.05,7.375 ; J1.3@9.95,3.25 11.05,4.35 pad.@11.05,7.375 ; C36.1 11.847,8.172 pad.@11.05,7.375
PH-INP: C37.1 J1.2 pad.@6.475,7.175 R24.1 | length 5.3
  TopLayer w0.5: J1.2@6.45,3.1 6.45,7.175 6.45,8.386 R24.1
RS485+: J3.3 R4.1 R5.2 U9.2 | length 7.3
  BottomLayer w0.5: R4.1 R5.2 13.438,65.435 U9.2 13.605,66.048 J3.3
RS485-: J3.4 R5.1 R17.1 U9.1 | length 7.7
  BottomLayer w0.5: J3.4 16.145,66.237 U9.1 14.962,65.054 R5.1 16.574,64.074 R17.1
RS485_A: J4.3 J5.3 | length 37.7
  TopLayer w0.5: J4.3 13.58,106.97 16.2,104.35 16.2,77.725 14.525,76.05 14.525,73.32 J5.3@13.63,72.425
RS485_B: J4.4 J5.4 | length 36.9
  TopLayer w0.5: J4.4 16.12,105.88 17.1,104.9 17.1,77.025 15.5,75.425 15.5,73.095 J5.4@16.17,72.425
RST#: P2.3 R14.2 U2.4 | length 17.5
  TopLayer w0.3: P2.3@2,46 2.65,45.35 4.874,45.35 6.549,43.675 12.125,43.675 v2(12.65,44.2)
  BottomLayer w0.3: U2.4 12.275,46.95 13.15,46.075 13.15,45.45 13.6,45 13.6,44.172 12.678,44.172 v2(12.65,44.2)
RX485: U2.10
SCK1: R10.2 U1.4 U2.12 | length 13.1
  TopLayer w0.3: R10.2 10.501,42.024 11.14,41.385 U1.4 11.125,39.26 v1(11.125,37.2)
  BottomLayer w0.3: U2.12 9.075,42.1 11.125,40.05 v1(11.125,37.2)
SPI_CS: U1.14 U5.3 | length 14.9
  TopLayer w0.3: U5.3 v2(9.809,21.691) ; v2(12.4,32.05) 12.4,30.014 U1.14
  BottomLayer w0.3: v2(9.809,21.691) 10.225,22.108 10.225,25.8 12.4,27.975 v2(12.4,32.05)
SPI_DIN: U1.12 U5.16 | length 5.6
  TopLayer w0.3: v2(7.975,27.2) 8.531,26.644 U5.16 ; v2(9.85,27.975) 9.85,29.984 U1.12
  BottomLayer w0.3: v2(7.975,27.2) 9.125,27.2 9.85,27.925 v2(9.85,27.975)
SPI_DOUT: U1.11 U5.15 | length 4.1
  TopLayer w0.25: U1.11 8.6,27.825 9.181,27.244 U5.15
SPI_SCLK: U1.13 U5.1 | length 10.8
  TopLayer w0.3: U5.1 8.525,20.295 v2(8.525,21.675) ; v2(11.14,28.015) U1.13
  BottomLayer w0.3: v2(8.525,21.675) 9.525,22.675 9.525,26.4 v2(11.14,28.015)
SSEL1: R12.2 U1.3 U2.11 | length 19.6
  TopLayer w0.25: R12.2 3.961,36.175 11.925,36.175 12.4,36.65 v1(12.4,37.15) 12.4,39.265 U1.3
  BottomLayer w0.25: U2.11 9.575,42.65 12.4,39.825 v1(12.4,37.15)
TP-IN+: J1.5 R3.1 R21.2 U5.11 | length 47
  TopLayer w0.3: U5.11 11.781,27.381 12.05,27.65 13.375,27.65 13.875,27.15 13.875,26.525 14.675,25.725 17.525,25.725
  TopLayer w0.5: J1.5@16.95,3.25 16.95,10.725 19.225,13 19.225,24.85 18.35,25.725 17.525,25.725
  BottomLayer w0.5: J1.5@16.95,3.25 16.575,3.625 16.575,11.6 18.399,13.424 R3.1
TP-IN-: J1.4 R21.1 R22.2 | length 13.7
  BottomLayer w0.5: J1.4@13.45,3.25 15.575,5.375 15.575,12.413 R21.1 R22.2
TX485: U2.9
VCC3.3: C1.1 C3.2 C4.1 C8.1 C10.1 C11.1 C12.1 C13.1 CA1.1 FB7.2 P2.1 P3V3.1 R1.1 R2.1 R6.1 R7.2 R9.1 R10.1 R12.1 R13.1 U1.1 U2.1 U2.6 U2.19 U2.27 U3.8 U4.3 | length 49.4
  TopLayer w0.3: P2.1 2.875,41.8 7.4,41.8 7.624,42.024 R10.1 R10.1@8.338,42.024 ; v2(12.1,49.1) v2(12.1,49.1) C10.1 ; v2(12.2,45.65) 12.974,46.424 C11.1
  TopLayer w0.4: C12.1@4.05,49.886 C12.1 4.038,48.512 v2(4.125,48.425) ; R13.1@4.05,51.625 v2(4.05,52.375) ; v2@4.138,44.413 v2(4.175,44.45) ; v2(16.726,41.026) R2.1
  TopLayer w0.5: R12.1 1.988,40.913 P2.1 ; C13.1@4.138,43.324 v2@4.138,44.413 ; P3V3.1@13.587,55.125 R1.1 R1.1@13.587,57.676 ; U1.1 15.751,38.474 C1.1 C3.2 v1(16.524,36.726)
  TopLayer w1: P3V3.1 14.275,54.575 FB7.2
  BottomLayer w0.3: v2(4.125,48.425) 4.1,48.45 U2.27 ; v2(4.175,44.45) U2.19 ; U2.6 11.925,45.95 12.2,45.675 v2(12.2,45.65) ; U2.1 11.7,48.45 v2@12.075,48.825
  BottomLayer w0.4: R7.2 13.065,51.613 13.327,51.875 v2(14.125,51.875) ; v1(16.725,44.35) 18.525,44.35 19.175,43.7 19.175,42.797 17.46,42.797 U4.3 ; v1(18.075,62.625) 19,62.625 19,59.92 U3.8
  BottomLayer w0.5: R6.1 1.988,40.913 P2.1 ; CA1.1 16.489,36.761 v1(16.524,36.726)
VDD_ISO: C2.1 C6.1 C14.1 C25.1 CA2.1 FB1.1 R23.2 U1.16 U5.13 U7.3 U15.1 U15.14 | length 19.4
  TopLayer w0.3: C25.1@2.27,10.45 U15.1 ; v2(5.2,15.375) 6.3,15.375 6.695,15.77 U15.14 ; U5.13 10.481,24.844 v2(10.925,24.4)
  TopLayer w0.5: v1(2.849,27.851) R23.2 ; U1.16 15.846,30.004 v1(16.651,29.199) C2.1
  BottomLayer w0.4: v2(10.925,24.4) 10.925,24.3 C14.1@11.675,23.55
  BottomLayer w0.5: FB1.1@4.549,20.975 v1(5.475,20.975) ; U7.3 16.001,25.437 C6.1 v1(19.126,26.374) ; CA2.1 16.449,29.401 v1(16.651,29.199)
  other v2: 3.2,10.45
VREF: C33.1 C35.1 FB2.2 U5.9 U15.9 | length 17
  TopLayer w0.35: U15.9 9.945,17.195 10.725,17.975 13.387,17.975 C33.1 ; U5.9 13.081,25.194 13.9,24.375 C35.1@15.875,24.375
  TopLayer w0.5: C33.1 13.438,18.413 v1(14.4,19.375) 15.463,20.438 15.463,23.963 C35.1@15.875,24.375
  BottomLayer w0.5: v1(14.4,19.375) 14.939,19.375 FB2.2
pads on no net: J6.1 J6.2 U1.7 U2.7 U2.15 U2.16 U2.20 U2.24 U2.32 U2.33 U2.34 U5.2 U5.4 U6.7 U6.9 U11.9 U11.11 U15.2 U15.3 U15.7

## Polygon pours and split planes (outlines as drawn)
no net on TopSolder "BottomLayer-No Net" (solid): 7.9,12.175 7.5,12.175 7.125,11.8 7.125,9.85 6.95,9.675 6.875,9.6 5.7,9.6 4.7,8.6 4.7,7.95 4.7,1.575 4.9,1.375 7.35,1.375 7.65,1.375 8.225,1.95 8.225,6.625 8.225,7.075 8.375,7.225 8.5,7.35 8.825,7.35 9.2,7.725 9.2,9.2 8.875,9.525 8.875,11.75 8.475,12.15
no net on BottomSolder "BottomLayer-No Net" (solid): 7.975,12.175 7.525,12.175 7.225,11.875 7.125,11.775 7.125,9.95 7.125,9.825 6.9,9.6 6.85,9.55 5.7,9.55 5.6,9.55 4.725,8.675 4.725,1.675 4.95,1.45 7.35,1.45 7.375,1.425 7.6,1.425 8.175,2 8.2,2.025 8.2,6.575 8.2,7.075 8.4,7.275 8.45,7.325 8.75,7.325 8.85,7.325 9.2,7.675 9.2,9.15 8.85,9.5 8.825,9.525 8.825,11.625 8.825,11.75 8.375,12.2
GND on TopLayer "BottomLayer-No Net" (hatched 90Degree grid 0.3 track 0.3, remove dead copper, pour order 4): 0.075,67.25 22.025,67.25 22.05,67.225 22.05,34.875 22.075,34.85 0.3,34.85 0.075,35.075
GND_ISO on TopLayer "BottomLayer-No Net" (hatched 90Degree grid 0.3 track 0.3, remove dead copper, pour order 10): -0.006,33.15 22.05,33.15 22.05,12.625 22,12.575 12.125,12.575 10.4,14.3 10.15,14.55 -0.006,14.55
GND on BottomLayer "BottomLayer-No Net" (hatched 90Degree grid 0.3 track 0.3, remove dead copper, pour order 6): -0.1,67.175 22,67.175 22.05,67.225 22.05,34.85 22,34.8 0.05,34.8 -0.075,34.925
GND_ISO on BottomLayer "BottomLayer-No Net" (hatched 90Degree grid 0.3 track 0.3, remove dead copper, pour order 8): -0.05,14.525 10.125,14.525 11.7,12.95 12.15,12.5 22.1,12.5 22.1,32.925 22.05,32.975 0.05,32.975 -0.05,32.875
24VGND_IN on GND (split plane): 21.49,92.777 0.505,92.777 0.505,109.54 21.49,109.54
GND_1 on GND (split plane): 21.49,73.152 0.505,73.152 0.505,91.273 21.49,91.273
GND on GND (split plane): 21.49,34.327 0.505,34.327 0.505,53.498 9.075,53.498 9.14,53.506 9.201,53.532 9.253,53.572 10.678,54.997 10.696,55.019 10.718,55.049 10.744,55.11 10.752,55.175 10.752,61.946 11.504,62.698 17,62.698 17.065,62.706 17.126,62.732 17.178,62.772 17.218,62.824 17.244,62.885 17.252,62.95 17.244,63.015 17.218,63.076 17.178,63.128 17.126,63.168 17.065,63.194 17,63.202 11.4,63.202 11.335,63.194 11.274,63.168 11.222,63.128 10.322,62.228 10.282,62.176 10.256,62.115 10.248,62.05 10.248,55.279 8.971,54.002 0.505,54.002 0.505,71.648 21.49,71.648
GND_ISO on GND (split plane): 21.49,0.485 0.505,0.485 0.505,33.523 21.49,33.523
+24V on PWR (split plane): 21.49,64.052 10.575,64.052 10.51,64.044 10.449,64.019 10.397,63.978 10.357,63.926 10.331,63.865 10.323,63.8 10.323,57.005 9.671,56.352 6.274,56.352 6.209,56.344 6.148,56.319 6.096,56.278 6.022,56.205 5.982,56.152 5.956,56.092 5.948,56.026 5.948,53.577 0.505,53.577 0.505,71.698 21.49,71.698
NetL3_2 on PWR (split plane): 21.49,92.802 0.505,92.802 0.505,109.54 21.49,109.54
NetC23_1 on PWR (split plane): 12.798,62.925 12.798,56.23 10.146,53.577 6.452,53.577 6.452,55.848 9.775,55.848 9.84,55.857 9.901,55.882 9.953,55.922 10.753,56.722 10.793,56.774 10.819,56.835 10.827,56.9 10.827,63.548 12.798,63.548
VCC3.3 on PWR (split plane): 21.49,34.327 0.505,34.327 0.505,53.073 10.275,53.073 10.34,53.082 10.401,53.107 10.453,53.147 10.493,53.199 10.502,53.221 13.154,55.873 13.176,55.882 13.228,55.922 13.268,55.974 13.294,56.035 13.302,56.1 13.302,63.548 21.49,63.548
+24V_1 on PWR (split plane): 21.49,73.202 0.505,73.202 0.505,91.298 21.49,91.298
VDD_ISO on PWR (split plane): 21.49,0.485 0.505,0.485 0.505,33.523 21.49,33.523

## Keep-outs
KeepOutLayer:
  lines w0.5: -0.006,0 -0.006,110.075 22,110.075 22,0 10.994,0 -0.006,0

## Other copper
TopLayer:
  pour cut-out: 6.425,60.575 10.4,60.575 10.4,56.525 6.45,56.525 6.425,56.55
GND (plane layer: these items are gaps in the copper):
  pour cut-out: 7.575,12.15 7.15,11.725 7.15,9.875 6.85,9.575 5.575,9.575 4.75,8.75 4.75,1.775 5.1,1.425 7.675,1.425 8.225,1.975 8.225,6.725 9.225,7.725 9.225,9.175 8.85,9.55 8.85,11.55 8.875,11.575 8.875,11.725 8.45,12.15
  lines w0.5: 0.025,53.75 9.075,53.75 10.5,55.175 10.5,62.05 11.4,62.95 17,62.95
  lines w0.8: -0.025,33.925 21.875,33.925
  lines w1.5: 0.094,72.4 22.15,72.4 ; 0.125,92.025 21.675,92.025
PWR (plane layer: these items are gaps in the copper):
  pour cut-out: 7.55,12.15 7.125,11.725 7.125,9.85 6.85,9.575 5.575,9.575 4.725,8.725 4.725,1.775 5.1,1.4 7.65,1.4 8.225,1.975 8.225,6.725 9.2,7.7 9.2,9.225 8.85,9.575 8.85,11.775 8.475,12.15
  lines w0.5: 0.175,53.325 6.2,53.325 ; 10.275,53.325 6.2,53.325 ; 13.05,56.1 13.05,63.8 ; 13.05,62.925 13.05,56.125 10.25,53.325 6.2,53.325 ; 22.125,63.8 13.05,63.8 ; 6.2,53.325 6.2,56.026 6.274,56.1 9.775,56.1 10.575,56.9 10.575,63.8 13.05,63.8
  lines w0.8: -0.025,33.925 22.1,33.925
  lines w1.5: 0.075,72.45 22.025,72.45 ; 0.3,92.05 21.675,92.05

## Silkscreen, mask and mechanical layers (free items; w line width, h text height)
TopOverlay:
  text "+ -  A B PE" at 10.325,67.175 h1
  text "SPSensor_V0.3" at 10.375,13.4 h1
  text "C32" at 11.625,5.825 h0.8
  text "GUA  IN  CMP  T-  T+" at 1.525,0.225 h1
Mechanical1:
  lines w0.2: 18.685,69.45 18.685,113.285
  lines w0.3: -4.65,71.55 22.875,71.55 ; -2,94.975 21.525,94.975 ; -1.206,3.075 26.45,3.075 ; -0.431,0.025 31.15,0.025 ; -0.075,69 4.175,69 ; 0.006,4.125 0.006,78.075 ; 2.45,64.05 2.45,111.35 ; 15.55,7.05 21.425,7.05 ; 19.5,-2.85 19.5,10.75

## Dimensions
-4.65,71.55 to -0.075,69 on Mechanical1
-1.3,94.975 to -0.675,92.425 on Mechanical1
2.45,70.075 to 0,68.65 on Mechanical1
-0.75,3.075 to -0.85,0.025 on Mechanical1
-0.006,4.75 to 21.975,-0.5 on Mechanical1
22.875,71.55 to 20.794,0.034 on Mechanical1
19.525,-2.725 to 21.975,-1.525 on Mechanical1
21.1,0.025 to 21.425,7.05 on Mechanical1
22.55,110.075 to 23.394,0.034 on Mechanical1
